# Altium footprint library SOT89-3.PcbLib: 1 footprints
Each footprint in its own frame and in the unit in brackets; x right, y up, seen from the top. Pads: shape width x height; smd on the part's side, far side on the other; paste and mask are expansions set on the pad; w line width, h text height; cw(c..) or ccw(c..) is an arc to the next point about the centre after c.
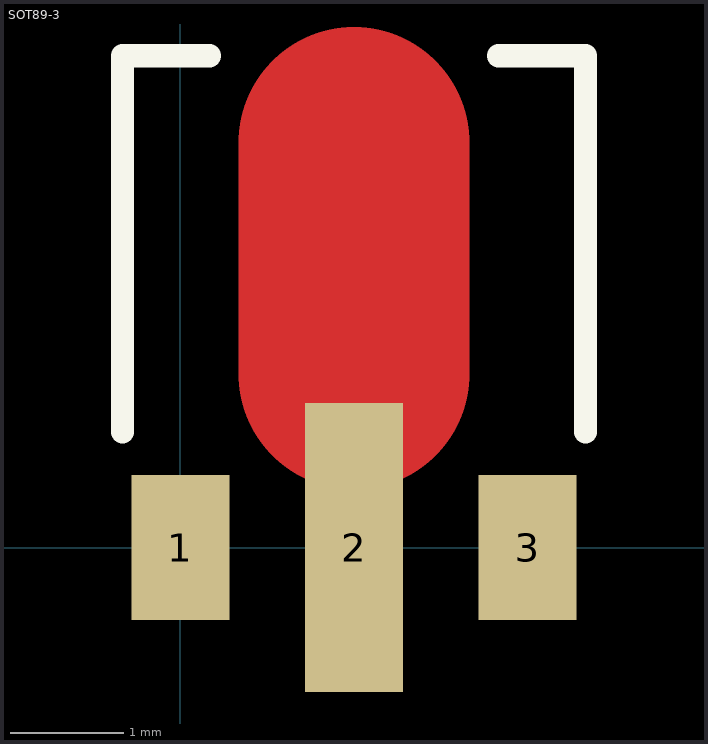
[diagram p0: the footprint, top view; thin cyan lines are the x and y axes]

## SOT89-3 [mil]
pads (3):
  rect 34x50 smd: 1(0,0) 3(120,0)
  rect 34x100 smd: 2(60,0)
Top Layer:
  lines w80: 60,60 60,140
Top Overlay:
  lines w8: -20,40 -20,170 10,170 ; 110,170 140,170 140,40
